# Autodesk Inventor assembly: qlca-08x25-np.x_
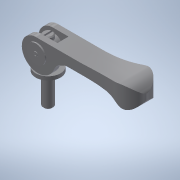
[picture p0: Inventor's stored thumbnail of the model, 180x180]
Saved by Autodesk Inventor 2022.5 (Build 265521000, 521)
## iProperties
Part Number: qlca-08x25-np.x_
Material: 一般
Document SubType Name: Assembly
Designer: ImaoCorp
Sending System: SOLIDWORKS 2017-2017317
MC: AMD64
MC_MODEL: Intel64 Family 6 Model 60 Stepping 3, GenuineIntel
OS: Windows_NT
FRU: Parasolid Version 29.0, build 201,  4-17-2017
FORMAT: text
GUISE: transmit
KEY: qlca-08x25-np
FILE: qlca-08x25-np.x_t
DATE: Wed Sep 04 15:47:38 2019
Author: ImaoCorp
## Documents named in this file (4)
- X:\14_SW2022-Inv2022\00_全2023-1023新製品(TCC)まで\q\qlca-08x25-np\QLCA-08X25-NP.iam
- X:\14_SW2022-Inv2022\00_全2023-1023新製品(TCC)まで\q\qlca-08x25-np\qlca-08x25-np_01.ipt
- X:\14_SW2022-Inv2022\00_全2023-1023新製品(TCC)まで\q\qlca-08x25-np\qlca-08x25-np_02.ipt
- X:\14_SW2022-Inv2022\00_全2023-1023新製品(TCC)まで\q\qlca-08x25-np\qlca-08x25-np_03.ipt
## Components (3 placed, 3 different names)
1. qlca-08x25-np_01
2. qlca-08x25-np_02
3. qlca-08x25-np_03
